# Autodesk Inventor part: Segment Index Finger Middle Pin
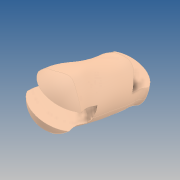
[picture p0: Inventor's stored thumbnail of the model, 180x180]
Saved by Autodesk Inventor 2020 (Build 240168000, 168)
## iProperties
Created: 2019-10
Part Number: Segment Index Finger Middle Pin
Material: GFRP
Document SubType Name: Modeling
Designer: yello
Density: 1.75 g/cm^3
Appearance: Default
Author: yello
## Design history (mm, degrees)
feature "Paliczek WS"
body "Solid1"
